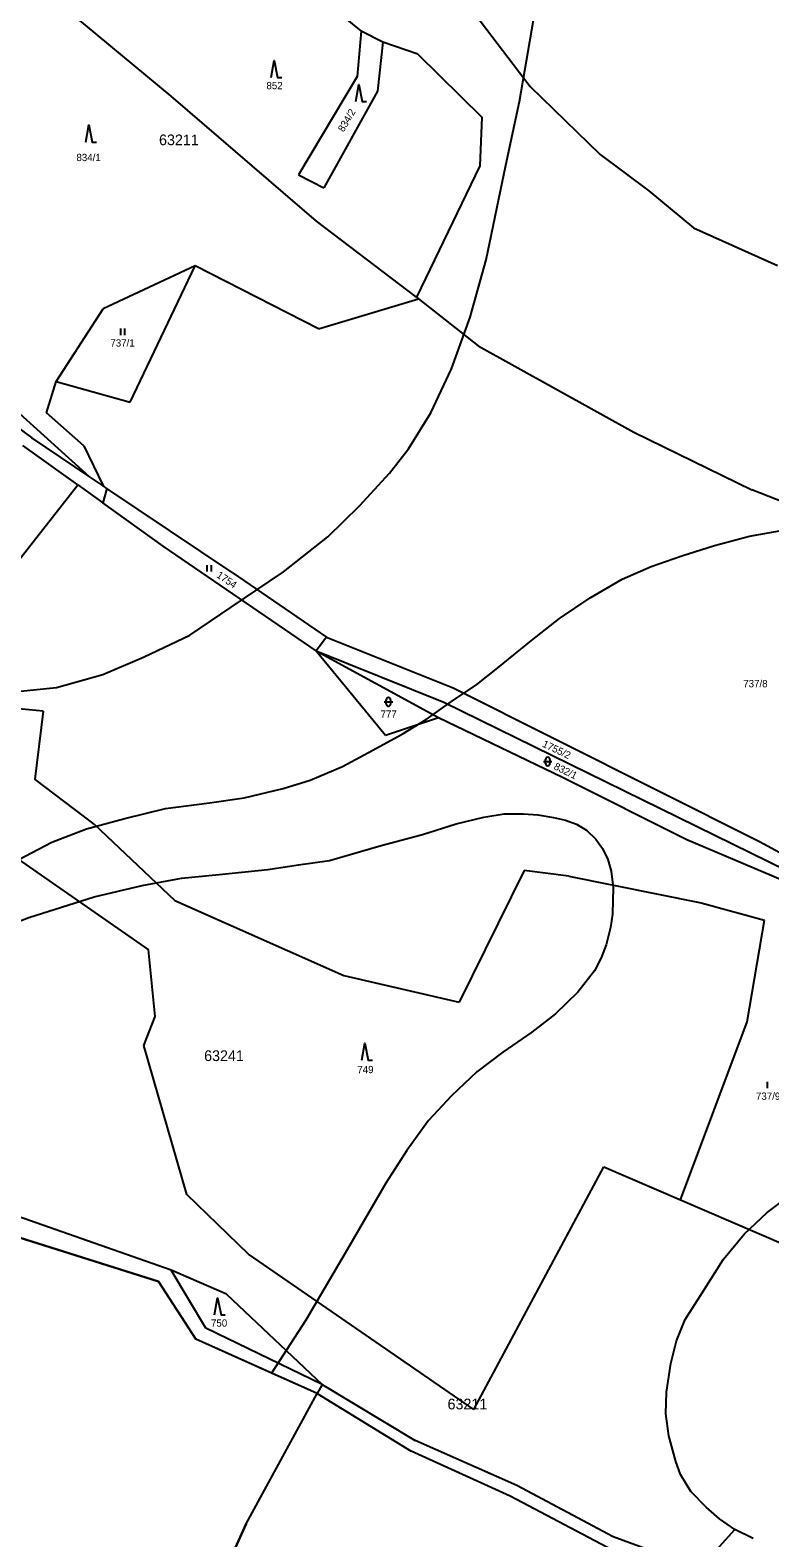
# Model space of a CAD drawing. Extents: x -546762 to -540209, y -1046851 to -1035694.
# Drawn here: x -543931.4 to -543758.3, y -1042427.6 to -1042074.7 of the extents above; entities that cross this region are included whole.
import ezdxf

# ---------------------------------------------------------------- set-up
doc = ezdxf.new("R2010")
doc.units = 0
for name, color, linetype in [('Vrstva 1', 7, 'Continuous'), ('Vrstva 18', 7, 'Continuous'), ('Vrstva 25', 7, 'Continuous'), ('Vrstva 52', 7, 'Continuous'), ('Vrstva 53', 7, 'Continuous'), ('Vrstva 6', 7, 'Continuous')]:
    doc.layers.add(name, color=color, linetype=linetype)

msp = doc.modelspace()

# ---------------------------------------------------------------- linework, layer by layer
at = {"layer": 'Vrstva 1'}
for points in [[(-543869.64, -1042062.06), (-543853.98, -1042074.92)], [(-543848.85, -1042077.52), (-543853.98, -1042074.92)], [(-543840.7, -1042080.32), (-543848.85, -1042077.52)], [(-543840.7, -1042080.32), (-543825.74, -1042095.05)], [(-543825.74, -1042095.05), (-543826.17, -1042106.48)], [(-543826.17, -1042106.48), (-543840.97, -1042137.22)], [(-543892.78, -1042129.89), (-543914.3, -1042139.9)], [(-543863.9, -1042144.59), (-543892.78, -1042129.89)], [(-543863.9, -1042144.59), (-543840.5, -1042137.59)], [(-543840.97, -1042137.22), (-543840.5, -1042137.59)], [(-543925.29, -1042156.91), (-543914.3, -1042139.9)], [(-543927.54, -1042164.29), (-543925.29, -1042156.91)], [(-543944.76, -1042159.95), (-543931.03, -1042170.11)], [(-543918.81, -1042172.01), (-543927.54, -1042164.29)], [(-543917.62, -1042179.17), (-543931.03, -1042170.11)], [(-543920.26, -1042181.13), (-543933.08, -1042171.93)], [(-543918.81, -1042172.01), (-543914.33, -1042181.39)], [(-543962.69, -1042235.19), (-543920.26, -1042181.13)], [(-543920.26, -1042181.13), (-543914.36, -1042185.36)], [(-543914.33, -1042181.39), (-543917.62, -1042179.17)], [(-543913.45, -1042181.98), (-543914.33, -1042181.39)], [(-543913.45, -1042181.98), (-543914.36, -1042185.36)], [(-543862.05, -1042216.8), (-543864.48, -1042219.95)], [(-543862.05, -1042216.8), (-543832.42, -1042228.61)], [(-543864.48, -1042219.95), (-543834.6, -1042231.98)], [(-543864.48, -1042219.95), (-543848.27, -1042239.75)], [(-543864.48, -1042219.95), (-543835.87, -1042235.6)], [(-543832.42, -1042228.61), (-543760.73, -1042264.59)], [(-543928.31, -1042234.14), (-543936.52, -1042233.35)], [(-543928.31, -1042234.14), (-543930.27, -1042250.01)], [(-543834.6, -1042231.98), (-543754.37, -1042271.37)], [(-543848.27, -1042239.75), (-543835.87, -1042235.6)], [(-543835.87, -1042235.6), (-543806.81, -1042249.52)], [(-543916.45, -1042260.58), (-543930.27, -1042250.01)], [(-543806.81, -1042249.52), (-543777.79, -1042264.12)], [(-543947.81, -1042259.32), (-543903.73, -1042289.95)], [(-543916.45, -1042260.58), (-543897.55, -1042278.4)], [(-543777.79, -1042264.12), (-543755.27, -1042273.64)], [(-543760.73, -1042264.59), (-543753.29, -1042268.67)], [(-543815.81, -1042271.42), (-543831.03, -1042302.2)], [(-543805.39, -1042272.75), (-543815.81, -1042271.42)], [(-543805.39, -1042272.75), (-543774.42, -1042278.94)], [(-543897.55, -1042278.4), (-543857.98, -1042296.01)], [(-543774.42, -1042278.94), (-543759.58, -1042283.06)], [(-543763.62, -1042306.82), (-543759.58, -1042283.06)], [(-543902.13, -1042305.57), (-543903.73, -1042289.95)], [(-543857.98, -1042296.01), (-543831.03, -1042302.2)], [(-543904.83, -1042312.41), (-543902.13, -1042305.57)], [(-543779.24, -1042348.49), (-543763.62, -1042306.82)], [(-543894.77, -1042347.22), (-543904.83, -1042312.41)], [(-543827.57, -1042397.56), (-543797.14, -1042340.78)], [(-543797.14, -1042340.78), (-543779.24, -1042348.49)], [(-543880.33, -1042361.24), (-543894.77, -1042347.22)], [(-543898.43, -1042364.97), (-543934.39, -1042352.3)], [(-543933.95, -1042357.29), (-543901.36, -1042367.58)], [(-543827.57, -1042397.56), (-543880.33, -1042361.24)], [(-543885.47, -1042370.59), (-543898.43, -1042364.97)], [(-543890.31, -1042378.58), (-543898.43, -1042364.97)], [(-543901.36, -1042367.58), (-543892.62, -1042381.13)], [(-543885.47, -1042370.59), (-543863.1, -1042391.76)], [(-543863.1, -1042391.76), (-543890.31, -1042378.58)], [(-543864.22, -1042393.81), (-543892.62, -1042381.13)], [(-543863.1, -1042391.76), (-543864.22, -1042393.81)], [(-543880.86, -1042424.34), (-543864.22, -1042393.81)], [(-543880.86, -1042424.34), (-543883.76, -1042430.75)]]:
    msp.add_lwpolyline(points, dxfattribs=at)
at = {"layer": 'Vrstva 25'}
for p, q in [((-543910.21, -1042146.06), (-543910.21, -1042144.56)), ((-543909.21, -1042146.06), (-543909.21, -1042144.56)), ((-543889.98, -1042201.43), (-543889.98, -1042199.93)), ((-543888.98, -1042201.43), (-543888.98, -1042199.93)), ((-543848.58, -1042231.94), (-543846.58, -1042231.94)), ((-543848.08, -1042232.44), (-543848.08, -1042231.44)), ((-543847.08, -1042231.44), (-543847.08, -1042232.44)), ((-543811.31, -1042245.89), (-543809.31, -1042245.89)), ((-543810.81, -1042246.39), (-543810.81, -1042245.39)), ((-543809.81, -1042245.39), (-543809.81, -1042246.39)), ((-543758.9, -1042322.38), (-543758.9, -1042320.88))]:
    msp.add_line(p, q, dxfattribs=at)
for points in [[(-543875.04, -1042085.81), (-543874.34, -1042081.81), (-543873.54, -1042085.81), (-543872.54, -1042085.81)], [(-543855.18, -1042091.38), (-543854.48, -1042087.38), (-543853.68, -1042091.38), (-543852.68, -1042091.38)], [(-543918.35, -1042100.89), (-543917.65, -1042096.89), (-543916.85, -1042100.89), (-543915.85, -1042100.89)], [(-543853.83, -1042315.79), (-543853.13, -1042311.79), (-543852.33, -1042315.79), (-543851.33, -1042315.79)], [(-543888.24, -1042375.43), (-543887.54, -1042371.43), (-543886.74, -1042375.43), (-543885.74, -1042375.43)]]:
    msp.add_lwpolyline(points, dxfattribs=at)
for centre, start, end in [((-543847.58, -1042231.44), 0, 180), ((-543847.58, -1042232.44), 180, 0), ((-543810.31, -1042245.39), 0, 180), ((-543810.31, -1042246.39), 180, 0)]:
    msp.add_arc(centre, 0.5, start, end, dxfattribs=at)
at = {"layer": 'Vrstva 52'}
for points in [[(-543952.56, -1042225.28), (-543947.11, -1042227.7), (-543941.06, -1042229.03), (-543934.4, -1042229.52), (-543925.19, -1042228.55), (-543914.41, -1042225.52), (-543904.72, -1042221.4), (-543894.07, -1042216.31), (-543884.38, -1042209.77), (-543872.15, -1042201.53), (-543861.73, -1042193.29), (-543854.34, -1042186.02), (-543847.32, -1042178.38), (-543842.84, -1042172.66), (-543837.63, -1042164.3), (-543832.79, -1042154), (-543828.43, -1042141.89), (-543824.67, -1042128.44), (-543820.07, -1042106.26), (-543816.92, -1042091.36), (-543810.39, -1042053.26), (-543805.94, -1042021.67), (-543804.24, -1042005.31), (-543803.62, -1041995.7)], [(-543937.12, -1042270.48), (-543926.34, -1042264.79), (-543918.23, -1042261.64), (-543909.27, -1042259.21), (-543899.7, -1042256.91), (-543889.4, -1042255.58), (-543881.29, -1042254.36), (-543872.21, -1042252.18), (-543865.91, -1042250.24), (-543858.28, -1042247.09), (-543852.22, -1042243.82), (-543844.35, -1042239.46), (-543838.78, -1042236.07), (-543832.85, -1042231.83), (-543826.91, -1042227.83), (-543821.94, -1042223.96), (-543814.07, -1042217.54), (-543807.53, -1042212.45), (-543800.38, -1042207.6), (-543792.87, -1042203.24), (-543786.09, -1042200.21), (-543778.95, -1042197.78), (-543771.32, -1042195.36), (-543763.08, -1042193.18), (-543755.21, -1042191.73)], [(-543963.35, -1042297.38), (-543958.92, -1042294.26), (-543955.08, -1042292.26), (-543941.88, -1042286.32), (-543931.71, -1042282.44), (-543916.45, -1042277.59), (-543905.18, -1042274.93), (-543895.98, -1042273.23), (-543887.14, -1042272.38), (-543875.76, -1042271.17), (-543868.61, -1042270.08), (-543861.34, -1042269.03), (-543849.3, -1042265.57), (-543839.61, -1042263.01), (-543831.72, -1042260.52), (-543825.22, -1042258.92), (-543820.51, -1042258.16), (-543815.94, -1042258.16), (-543812.62, -1042258.37)], [(-543812.62, -1042258.37), (-543808.95, -1042258.99), (-543806.18, -1042259.62), (-543803.55, -1042260.59), (-543801.27, -1042261.97), (-543799.06, -1042264.05), (-543797.46, -1042266.26), (-543796.22, -1042268.83), (-543795.46, -1042271.6), (-543794.97, -1042275.4), (-543795.04, -1042278.45), (-543795.18, -1042281.64), (-543795.6, -1042284.75), (-543796.63, -1042288.84), (-543797.81, -1042291.88), (-543799.4, -1042294.93), (-543803.28, -1042299.9), (-543808.49, -1042304.99), (-543814.06, -1042309.23), (-543820.84, -1042313.95), (-543826.89, -1042318.56), (-543832.83, -1042324.13), (-543838.16, -1042329.95), (-543843.24, -1042336.98), (-543848.21, -1042344.61), (-543857.12, -1042360.01), (-543866.87, -1042376.69), (-543874.9, -1042389.04)], [(-543874.9, -1042389.04), (-543892.62, -1042381.13), (-543901.36, -1042367.58), (-543933.95, -1042357.29), (-543960.63, -1042339.97), (-543986.21, -1042322.51)], [(-543766.5, -1042425.67), (-543770.1, -1042423.18), (-543773.22, -1042420.48), (-543776.82, -1042416.74), (-543779.24, -1042412.79), (-543780.35, -1042409.74), (-543781.94, -1042403.72), (-543782.7, -1042398.6), (-543782.49, -1042393.54), (-543781.53, -1042386.85), (-543780.2, -1042381.52), (-543778.14, -1042376.55), (-543774.14, -1042370.25), (-543769.18, -1042362.37), (-543764.33, -1042356.56), (-543759, -1042351.47), (-543750.16, -1042344.8), (-543739.87, -1042338.38), (-543729.33, -1042333.41), (-543723.62, -1042331.97), (-543716.84, -1042330.76), (-543704.6, -1042329.79), (-543695.4, -1042329.79)], [(-543911.35, -1042469.41), (-543914, -1042467.7), (-543909.21, -1042463.84), (-543892.75, -1042450.56), (-543884.95, -1042433.37), (-543883.76, -1042430.75), (-543880.86, -1042424.34), (-543864.22, -1042393.81), (-543874.9, -1042389.04)], [(-543792.12, -1042454.05), (-543766.5, -1042425.67)], [(-543762.28, -1042427.75), (-543766.5, -1042425.67)]]:
    msp.add_lwpolyline(points, dxfattribs=at)
at = {"layer": 'Vrstva 6'}
for points in [[(-543836.34, -1042059.01), (-543814.39, -1042087.86)], [(-543898.4, -1042090.18), (-543924.4, -1042068.64)], [(-543853.98, -1042074.92), (-543854.9, -1042085.52)], [(-543848.85, -1042077.52), (-543850.12, -1042088.98)], [(-543854.9, -1042085.52), (-543868.58, -1042108.56)], [(-543850.12, -1042088.98), (-543862.68, -1042111.62)], [(-543814.39, -1042087.86), (-543798.01, -1042103.79)], [(-543864.38, -1042119.4), (-543898.4, -1042090.18)], [(-543798.01, -1042103.79), (-543786.63, -1042112.3)], [(-543868.58, -1042108.56), (-543862.68, -1042111.62)], [(-543786.63, -1042112.3), (-543776.18, -1042120.97)], [(-543840.97, -1042137.22), (-543864.38, -1042119.4)], [(-543776.18, -1042120.97), (-543756.58, -1042129.82)], [(-543907.96, -1042161.76), (-543892.78, -1042129.89)], [(-543840.5, -1042137.59), (-543826.57, -1042148.56)], [(-543826.57, -1042148.56), (-543790.13, -1042168.82)], [(-543944.53, -1042154.84), (-543917.62, -1042179.17)], [(-543925.29, -1042156.91), (-543907.96, -1042161.76)], [(-543790.13, -1042168.82), (-543762.52, -1042182.32)], [(-543884.1, -1042201.66), (-543913.45, -1042181.98)], [(-543722.58, -1042198.01), (-543762.52, -1042182.32)], [(-543900.27, -1042195.47), (-543914.36, -1042185.36)], [(-543864.48, -1042219.95), (-543900.27, -1042195.47)], [(-543884.1, -1042201.66), (-543862.05, -1042216.8)], [(-543779.24, -1042348.49), (-543754.6, -1042359.1)], [(-543863.1, -1042391.76), (-543841.28, -1042404.86)], [(-543864.22, -1042393.81), (-543842.23, -1042407.35)], [(-543819.06, -1042417.83), (-543842.23, -1042407.35)], [(-543817.56, -1042415.34), (-543841.28, -1042404.86)], [(-543793.69, -1042431.31), (-543819.06, -1042417.83)], [(-543795.02, -1042427.4), (-543817.56, -1042415.34)], [(-543766.5, -1042437.88), (-543795.02, -1042427.4)]]:
    msp.add_lwpolyline(points, dxfattribs=at)

# ---------------------------------------------------------------- texts
at = {"layer": 'Vrstva 18'}
for s, p in [('852', (-543876.11, -1042088.51)), ('834/1', (-543920.56, -1042105.34)), ('737/1', (-543912.62, -1042148.76)), ('737/8', (-543764.56, -1042228.51)), ('777', (-543849.41, -1042235.64)), ('749', (-543854.85, -1042318.85)), ('737/9', (-543761.59, -1042325.08)), ('750', (-543889.08, -1042378.19))]:
    msp.add_text(s, height=1.7, dxfattribs=at).set_placement(p)
for s, rotation, p in [('834/2', 59.527, (-543858.05, -1042098.67)), ('1754', 325.8709, (-543887.95, -1042202.63)), ('1755/2', 334.5913, (-543811.72, -1042242.37)), ('832/1', 334.0319, (-543809.04, -1042247.61))]:
    msp.add_text(s, height=1.7, rotation=rotation, dxfattribs=at).set_placement(p)
at = {"layer": 'Vrstva 53'}
for s, p in [('63211', (-543901.24, -1042101.62)), ('63241', (-543890.69, -1042316.01)), ('63211', (-543833.74, -1042397.55))]:
    msp.add_text(s, height=2.5, dxfattribs=at).set_placement(p)

doc.saveas('drawing.dxf')
